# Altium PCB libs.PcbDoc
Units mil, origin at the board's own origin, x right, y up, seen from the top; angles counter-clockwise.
Board outline 2362.2 x 1574.8 mil, 2 copper layers (Top Layer, Bottom Layer); 7 components, 9 nets, 22 pads, 0 vias.
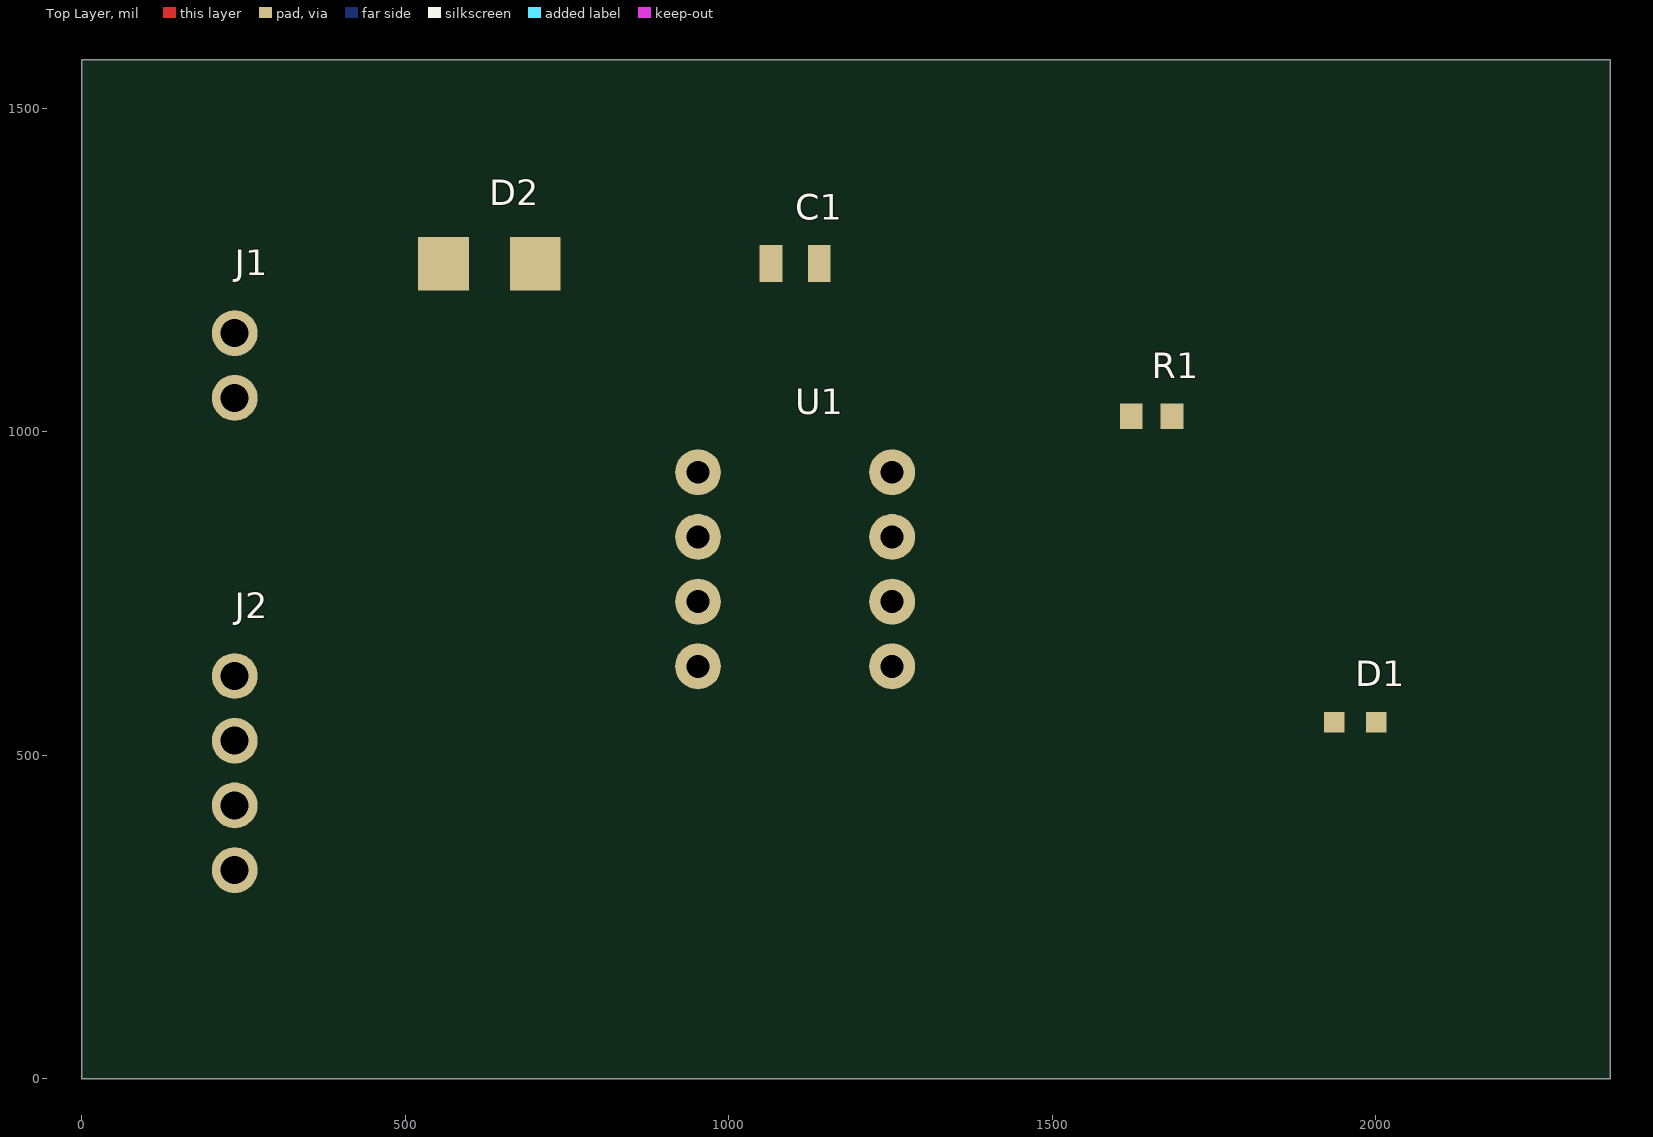
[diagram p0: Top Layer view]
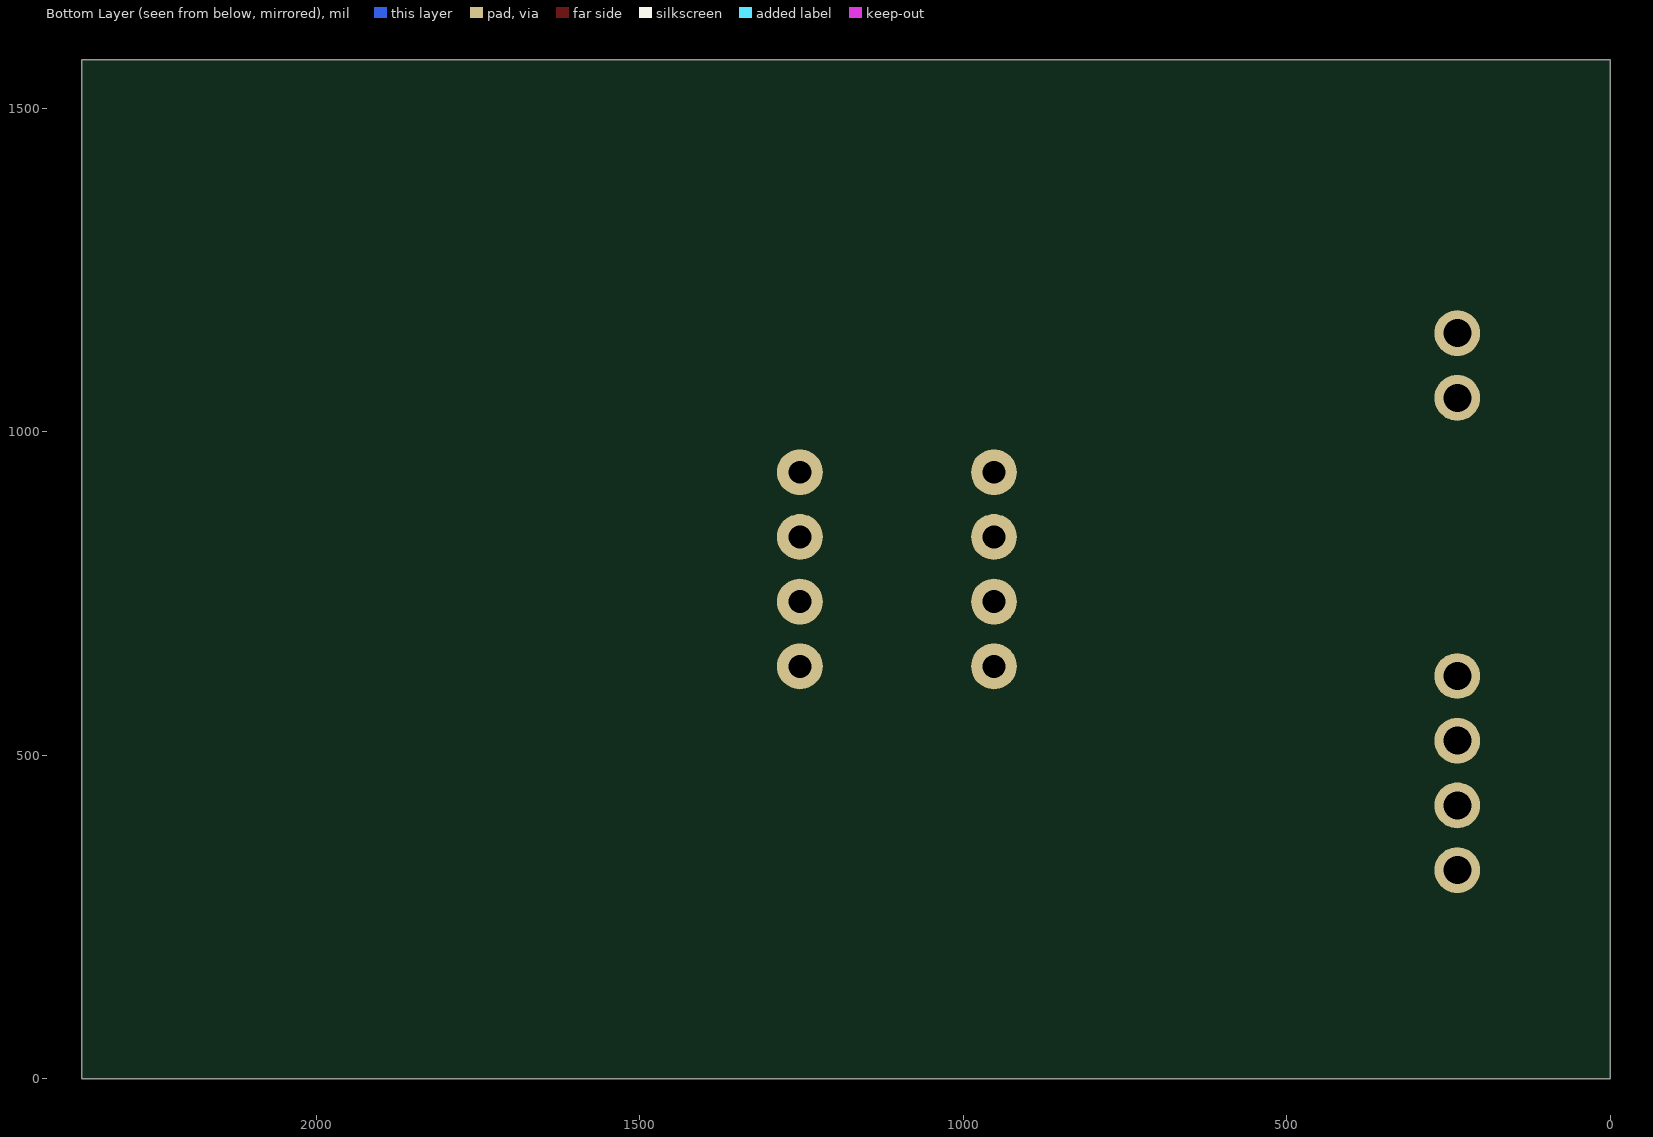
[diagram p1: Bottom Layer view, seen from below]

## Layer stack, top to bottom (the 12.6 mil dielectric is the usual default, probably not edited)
Top Solder: solder mask 0.4, Solder Resist, Dk 3.5
Top Layer: signal copper 1.4
Dielectric 1: dielectric 12.6, FR-4, Dk 4.8
Bottom Layer: signal copper 1.4
Bottom Solder: solder mask 0.4, Solder Resist, Dk 3.5

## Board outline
0,1574.8 2362.2,1574.8 2362.2,0 0,0

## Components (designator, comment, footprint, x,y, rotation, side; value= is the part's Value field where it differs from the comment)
C1 "100n" Chip_0805 1102.36,1259.84 r0 top
D1 "red" LED0603_Kingbright_APT1608SURCK 1968.5,551.18 r0 top
D2 "rectifier" DO214AC 629.92,1259.84 r0 top
J1 "SUPPLY" Header_1x2_P2.54 236.22,1102.36 r0 top
J2 "PORT" Header_1x4_P2.54 236.22,472.44 r0 top
R1 "330" Chip_0603 1653.54,1023.62 r0 top
U1 "MCU" DIP8_Microchip_P 1102.36,787.4 r0 top locked

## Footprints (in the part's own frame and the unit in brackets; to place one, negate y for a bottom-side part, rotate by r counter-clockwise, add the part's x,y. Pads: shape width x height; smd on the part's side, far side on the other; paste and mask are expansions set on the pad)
Chip_0603 [mm]
  rect 0.9x1 smd: 1(-0.8,0) 2(0.8,0)
Chip_0805 [mm]
  rect 0.9x1.45 smd: 1(-0.95,0) 2(0.95,0)
DIP8_Microchip_P [mm]
  round 1.8 hole 0.9: 1(-3.81,-3.81) 2(-3.81,-1.27) 3(-3.81,1.27) 4(-3.81,3.81) 5(3.81,3.81) 6(3.81,1.27) 7(3.81,-1.27) 8(3.81,-3.81)
DO214AC [mm]
  rect 2x2.1 smd: 1(-1.8,0) 2(1.8,0)
Header_1x2_P2.54 [mm]
  round 1.8 hole 1.1: 1(0,-1.27) 2(0,1.27)
Header_1x4_P2.54 [mm]
  round 1.8 hole 1.1: 1(0,-3.81) 2(0,-1.27) 3(0,1.27) 4(0,3.81)
LED0603_Kingbright_APT1608SURCK [mm]
  rect 0.8x0.8 smd: 1(-0.825,0) 2(0.825,0)

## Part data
C1: library part Capacitor
D1: library part LED
D2: library part Diode
J1: library part Connector_2
J2: library part Connector_4
R1: library part Resistor
U1: library part Microcontroller

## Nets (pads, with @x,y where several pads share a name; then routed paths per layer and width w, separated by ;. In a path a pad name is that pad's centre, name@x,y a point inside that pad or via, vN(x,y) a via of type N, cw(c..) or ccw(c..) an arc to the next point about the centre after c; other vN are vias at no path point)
GND: C1.2 D1.1 J1.2 U1.8
LED_A: D1.2 R1.2
LED_DRV: R1.1 U1.2
P0: J2.1 U1.3
P1: J2.2 U1.4
P2: J2.3 U1.5
P3: J2.4 U1.6
VCC: C1.1 D2.1 U1.1
VIN: D2.2 J1.1
pads on no net: U1.7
